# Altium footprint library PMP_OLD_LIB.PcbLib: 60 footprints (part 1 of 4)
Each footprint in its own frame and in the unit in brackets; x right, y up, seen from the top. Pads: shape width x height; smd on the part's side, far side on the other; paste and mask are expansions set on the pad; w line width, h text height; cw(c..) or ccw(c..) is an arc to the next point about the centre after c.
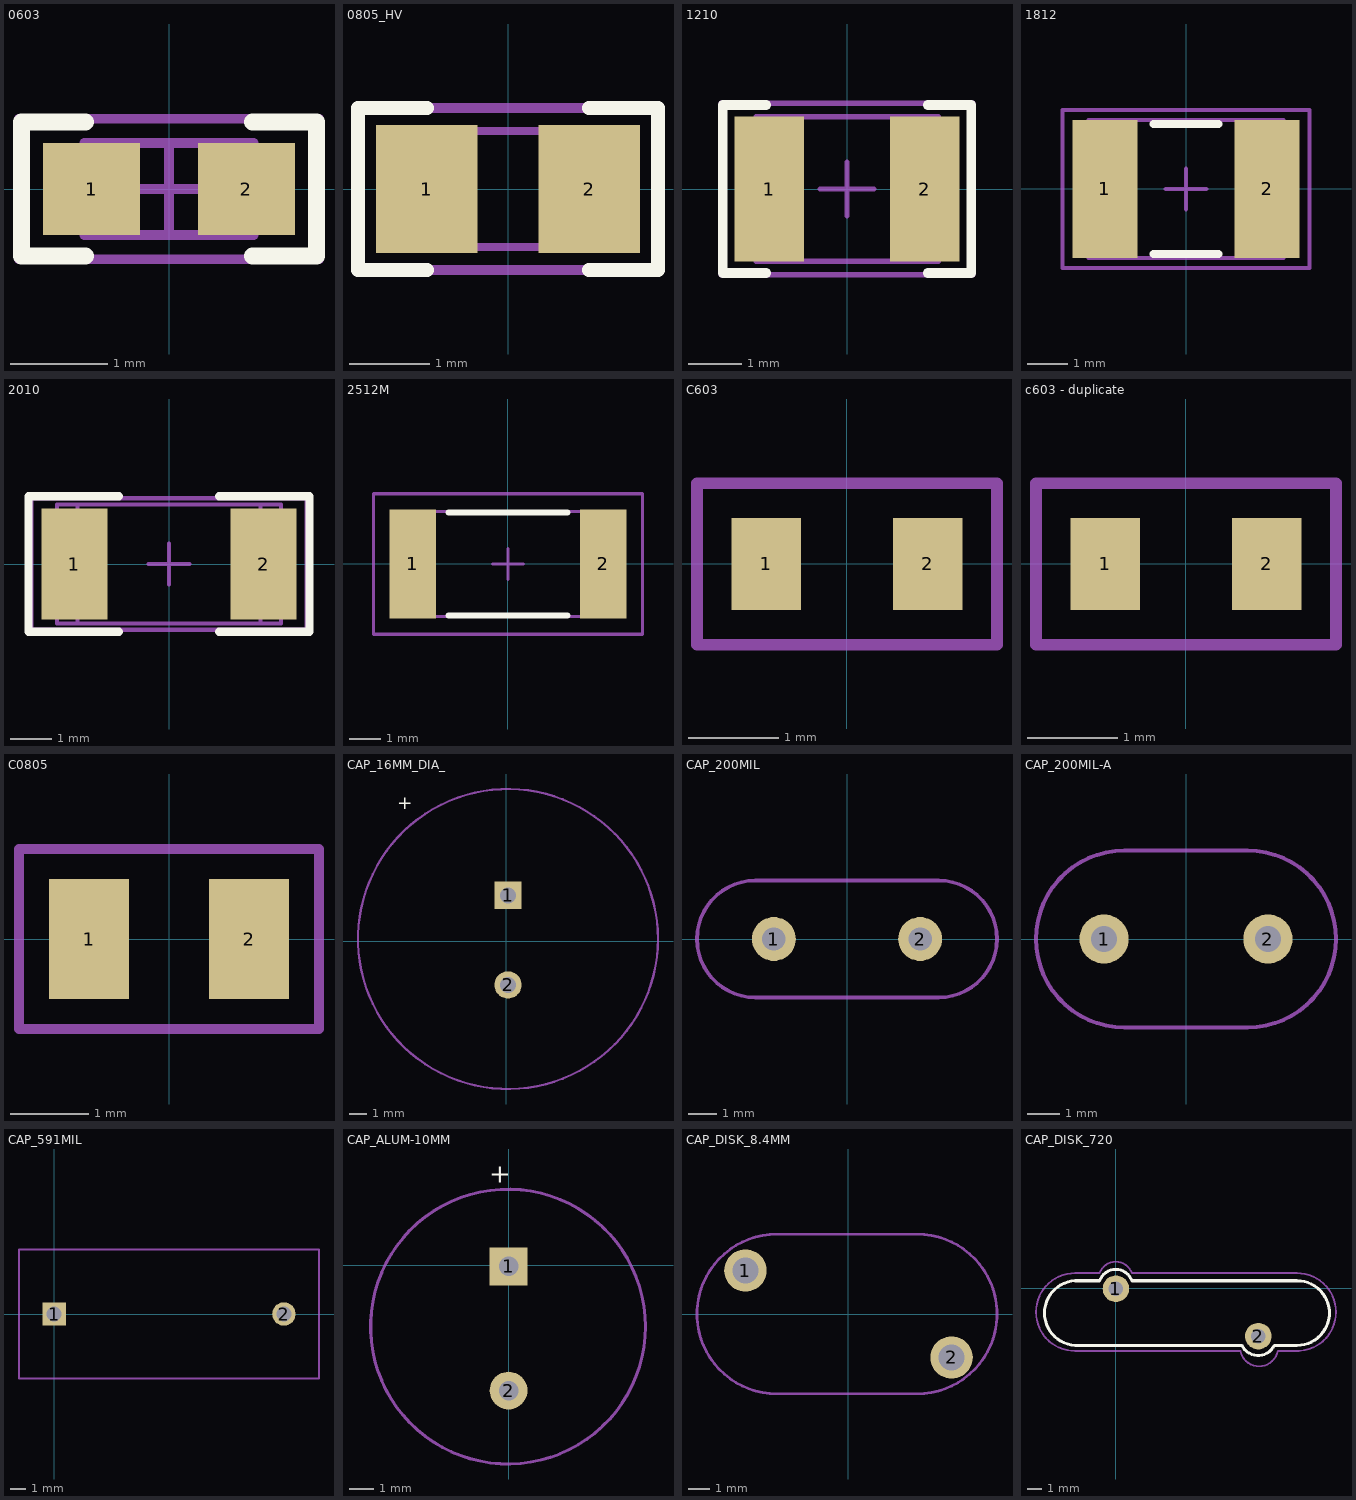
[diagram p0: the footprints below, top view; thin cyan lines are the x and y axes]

## 0603 [mm] "0603 from SM-752 data"
height 0.85
pads (2):
  rect 1x0.95 smd: 1(-0.8,0) 2(0.8,0)
Top Overlay:
  lines w0.178: -0.864,-0.691 -1.524,-0.691 -1.524,0.693 -0.864,0.693 ; 0.864,-0.691 1.524,-0.691 1.524,0.693 0.864,0.693
Mechanical 5:
  lines w0.1: -1.55,-0.725 1.55,-0.725 1.55,0.725 -1.55,0.725 -1.55,-0.725
  text ".Designator" at -0.864,1.067 h1.02
Mechanical 13:
  lines w0.1: -0.55,-0.475 -0.55,0.475 ; 0.55,-0.475 0.55,0.475 ; -0.875,-0.475 -0.875,0.475 0.875,0.475 0.875,-0.475 -0.875,-0.475
Mechanical 15:
  lines w0.1: -0.475,0 0.475,0 ; 0,-0.475 0,0.475 ; -1.55,-0.725 -1.55,0.725 1.55,0.725 1.55,-0.725 -1.55,-0.725
3D body: height 0.85, standoff 0, extent 0.551,-0.474 0.874,0.474
3D body: height 0.85, standoff 0, extent -0.549,-0.474 0.549,0.474
3D body: height 0.85, standoff 0, extent -0.874,-0.474 -0.551,0.474

## 0805_HV [mil] "0805 with 30mil clearance between pads"
height 43.31
pads (2):
  rect 50x63 smd: 1(-40,0) 2(40,0)
Top Overlay:
  lines w7: -40,-40 -74,-40 -74,0 -74,40 -40,40 ; 40,-40 74,-40 74,0 74,40 40,40
Mechanical 5:
  lines w5: -74,-40 -74,40 74,40 74,-40 -74,-40
  text ".Designator" at 229,-20 h60
Mechanical 13:
  lines w3.94: -25.59,-28.54 -25.59,28.54 ; 25.59,-28.54 25.59,28.54 ; -43.31,-28.54 43.31,-28.54 43.31,28.54 -43.31,28.54 -43.31,-28.54
3D body: height 43.31, standoff 0, extent -43.29,-28.52 -25.61,28.52
3D body: height 43.31, standoff 0, extent -25.57,-28.52 25.57,28.52
3D body: height 43.31, standoff 0, extent 25.61,-28.52 43.29,28.52

## 1210 [mm] "1210 from SM-752 data"
height 1.35
pads (2):
  rect 1.3x2.7 smd: 1(-1.45,0) 2(1.45,0)
Top Overlay:
  lines w0.178: -1.511,-1.568 -2.316,-1.568 -2.316,1.568 -1.511,1.568 ; 1.511,-1.568 2.316,-1.568 2.316,1.568 1.511,1.568
Mechanical 5:
  lines w0.1: -1.7,-1.35 1.7,-1.35 1.7,1.35 -1.7,1.35 -1.7,-1.35
  text ".Designator" at -1.905,-3.556 h1.52
Mechanical 13:
  lines w0.1: -1.2,-1.35 -1.2,1.35 ; 1.2,-1.35 1.2,1.35 ; -1.7,-1.35 -1.7,1.35 1.7,1.35 1.7,-1.35 -1.7,-1.35
Mechanical 15:
  lines w0.1: -0.5,0 0.5,0 ; 0,-0.5 0,0.5 ; -2.35,-1.6 -2.35,1.6 2.35,1.6 2.35,-1.6 -2.35,-1.6
3D body: height 1.35, standoff 0, extent -1.699,-1.349 -1.201,1.349
3D body: height 1.35, standoff 0, extent -1.199,-1.349 1.199,1.349
3D body: height 1.35, standoff 0, extent 1.201,-1.349 1.699,1.349

## 1812 [mm]
height 1.35
pads (2):
  rect 1.6x3.4 smd: 1(-2,0) 2(2,0)
Top Overlay:
  lines w0.2: -0.8,-1.6 0.8,-1.6 ; -0.8,1.6 0.8,1.6
Mechanical 5:
  lines w0.1: -2.4,-1.7 -2.4,1.7 2.4,1.7 2.4,-1.7 -2.4,-1.7
  text ".Designator" at 2.032,3.937 h1.52
Mechanical 13:
  lines w0.1: -1.9,-1.7 -1.9,1.7 ; 1.9,-1.7 1.9,1.7 ; -2.4,-1.7 2.4,-1.7 2.4,1.7 -2.4,1.7 -2.4,-1.7
Mechanical 15:
  lines w0.1: -0.5,0 0.5,0 ; 0,-0.5 0,0.5 ; -3.05,-1.95 3.05,-1.95 3.05,1.95 -3.05,1.95 -3.05,-1.95
3D body: height 1.35, standoff 0, extent 1.901,-1.699 2.399,1.699
3D body: height 1.35, standoff 0, extent -1.899,-1.699 1.899,1.699
3D body: height 1.35, standoff 0, extent -2.399,-1.699 -1.901,1.699

## 2010 [mm] "Chip Capacitor, Body 5.08x2.54mm, IPC Medium Density"
height 1.66
pads (2):
  rect 1.6x2.7 smd: 1(-2.3,0) 2(2.3,0)
Top Overlay:
  lines w0.2: -1.219,-1.65 -3.419,-1.65 -3.419,1.65 -1.219,1.65 ; 1.219,-1.65 3.419,-1.65 3.419,1.65 1.219,1.65
Mechanical 5:
  lines w0.1: -2.73,-1.45 -2.73,1.45 2.73,1.45 2.73,-1.45 -2.73,-1.45
  text ".Designator" at 5.461,-1.219 h1.52
Mechanical 13:
  lines w0.1: -2.23,-1.45 -2.23,1.45 ; 2.23,-1.45 2.23,1.45 ; -2.73,-1.45 2.73,-1.45 2.73,1.45 -2.73,1.45 -2.73,-1.45
Mechanical 15:
  lines w0.1: -0.5,0 0.5,0 ; 0,-0.5 0,0.5 ; -3.35,-1.6 3.35,-1.6 3.35,1.6 -3.35,1.6 -3.35,-1.6
3D body: height 1.66, standoff 0, extent -2.729,-1.449 -2.231,1.449
3D body: height 1.66, standoff 0, extent -2.229,-1.449 2.229,1.449
3D body: height 1.66, standoff 0, extent 2.231,-1.449 2.729,1.449

## 2512M [mm] "Chip Resistor, Body 6.3x3.2mm, IPC Low Density"
height 0.71
pads (2):
  rect 1.5x3.5 smd: 1(-3.05,0) 2(3.05,0)
Top Overlay:
  lines w0.2: -1.9,-1.65 1.9,-1.65 ; -1.9,1.65 1.9,1.65
Mechanical 5:
  lines w0.1: -3.225,-1.675 3.225,-1.675 3.225,1.675 -3.225,1.675 -3.225,-1.675
  text ".Designator" at 1.778,3.81 h1.52
Mechanical 13:
  lines w0.1: -2.463,-1.675 -2.463,1.675 ; 2.463,-1.675 2.463,1.675 ; -3.225,-1.675 3.225,-1.675 3.225,1.675 -3.225,1.675 -3.225,-1.675
Mechanical 15:
  lines w0.1: -0.5,0 0.5,0 ; 0,-0.5 0,0.5 ; -4.3,-2.25 4.3,-2.25 4.3,2.25 -4.3,2.25 -4.3,-2.25
3D body: height 0.71, standoff 0, extent -3.224,-1.674 -2.464,1.674
3D body: height 0.71, standoff 0, extent -2.462,-1.674 2.462,1.674
3D body: height 0.71, standoff 0, extent 2.464,-1.674 3.224,1.674

## C603 [mil]
pads (2):
  rect 30x40 smd mask+2: 1(-35,0) 2(35,0)
Mechanical 5:
  lines w5: -65,-35 -65,35 65,35 65,-35 -65,-35
  text ".Designator" at 265,30 h60

## c603 - duplicate [mil]
pads (2):
  rect 30x40 smd mask+2: 1(-35,0) 2(35,0)
Mechanical 5:
  lines w5: -65,-35 -65,35 65,35 65,-35 -65,-35
  text ".Designator" at -85,-135 h60

## C0805 [mil]
pads (2):
  rect 40x60 smd: 1(-40,0) 2(40,0)
Mechanical 5:
  lines w5: -75,-45 -75,45 75,45 75,-45 -75,-45
  text ".Designator" at -111,23 h60

## CAP_16MM_DIA_ [mil]
pads (2):
  rect 60x60 hole 35 mask+5: 1(3.4,100.6)
  round 60 hole 35 mask+5: 2(3.4,-96.4)
Top Overlay:
  text "+" at -240,290 h30
Mechanical 5:
  circle w5: c3.4,4.6 r330
  text "+" at -240,290 h30
  text ".Designator" at -85,-450 h60

## CAP_200MIL [mil]
pads (2):
  round 60 hole 32 mask+5: 1(-100,0) 2(100,0)
Mechanical 5:
  lines w5: -125,-80 cw(c-125,0) -125,80 125,80 cw(c125,0) 125,-80 -125,-80
  text ".Designator" at -235,15 h60

## CAP_200MIL-A [mil]
pads (2):
  round 60 hole 32: 1(-100,0) 2(100,0)
Mechanical 5:
  lines w5: 74,-108 -75,-108 cw(c-75,0) -75,108 74,108 ; 75,-108 ccw(c75,0) 75,108
  text ".Designator" at 195,90 h60

## CAP_591MIL [mil]
pads (2):
  rect 60x60 hole 38: 1(0,0)
  round 60 hole 38: 2(590,0)
Mechanical 5:
  lines w5: -90,-165 -90,165 680,165 680,-165 -90,-165
  text ".Designator" at 175,210 h60

## CAP_ALUM-10MM [mil]
pads (2):
  rect 60x60 hole 31: 1(0,-2)
  round 60 hole 31: 2(0,-199)
Top Overlay:
  text "+" at -30.47,130.46 h30
Mechanical 5:
  circle w5: c-1,-97.5 r218
  text "+" at -31.52,132.02 h30
  text ".Designator" at -290,110 h60

## CAP_DISK_8.4MM [mil]
pads (2):
  round 77 hole 47: 1(-187,79) 2(187.5,-79)
Mechanical 5:
  lines w5: -130,-145 cw(c-130,0) -130,145 125,145 cw(c125,0) 125,-145 -130,-145
  text ".Designator" at 90,-170 h60

## CAP_DISK_720 [mil]
pads (2):
  round 70 hole 38: 1(0,-1) 2(375,-126)
Top Overlay:
  lines w8: -98,-150 332,-150 ccw(c374.5,-130) 417,-150 477,-150 ccw(c477,-65) 477,20 42,20 ; -98,20 -43,20 ; -97.95,-150 cw(c-103,-65) -97.95,20 ; -43.01,19.97 cw(c-0.5,5) 42.01,19.97
Mechanical 5:
  lines w5: -43.01,39.97 cw(c-0.5,25) 42.01,39.97 ; -43,40 -108,40 ccw(c-108,-62.5) -108,-165 327,-165 ; 42,40 477,40 cw(c477,-62.5) 477,-165 ; 327.72,-164.85 ccw(c377,-155) 426.28,-164.85 ; 427,-165 482,-165
  text ".Designator" at 150,-377 h60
